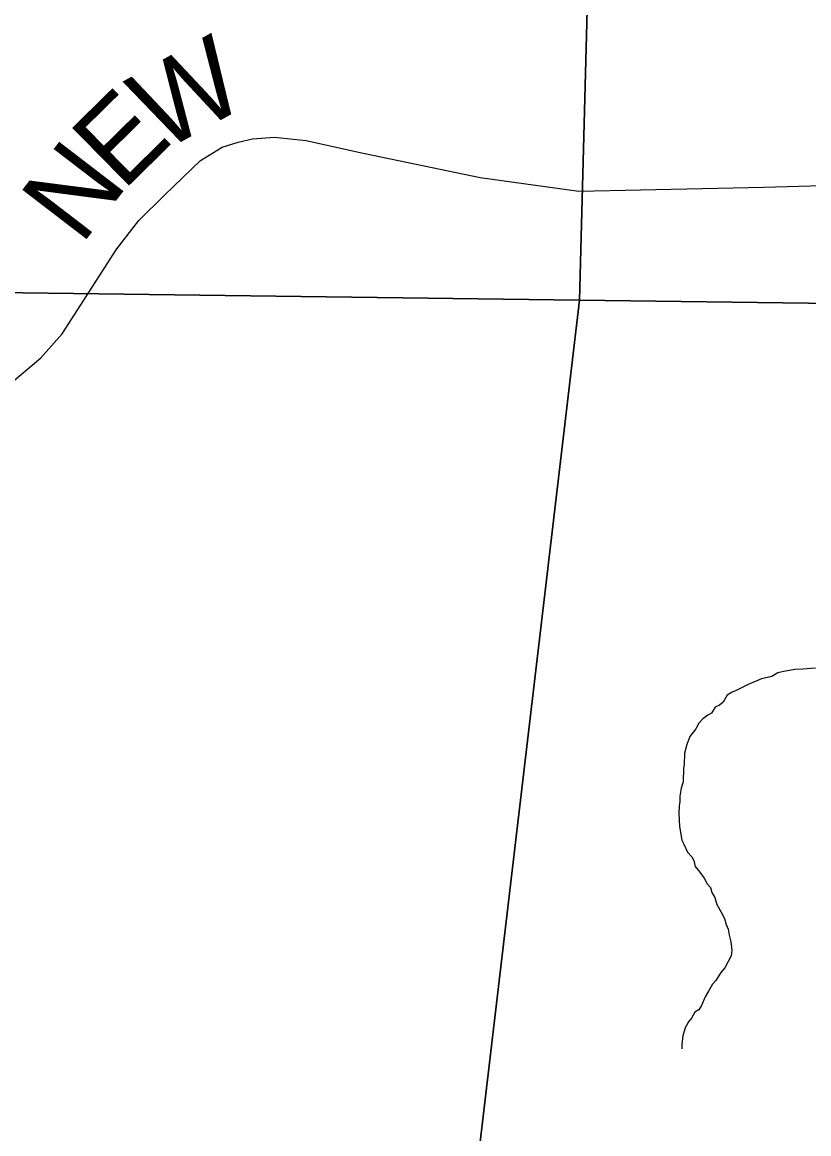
# Model space of a CAD drawing. Extents: x 0 to 34, y -2.3 to 22.
# Drawn here: x 3.123 to 3.675, y 15.821 to 16.601 of the extents above; entities that cross this region are included whole.
import ezdxf

# ---------------------------------------------------------------- set-up
doc = ezdxf.new("R2010")
doc.units = 0
for name, color, linetype in [('GM_X_County_Road', 7, 'Continuous'), ('GM_X_County_Road_Text', 7, 'Continuous'), ('GM_X_Minor_River', 7, 'Continuous'), ('GM_X_Section', 7, 'Continuous')]:
    doc.layers.add(name, color=color, linetype=linetype)

msp = doc.modelspace()

# ---------------------------------------------------------------- linework, layer by layer
at = {"layer": 'GM_X_County_Road'}
for p, q in [((3.26354, 16.51301), (3.27486, 16.51647)), ((3.27486, 16.51647), (3.28493, 16.51883)), ((3.28493, 16.51883), (3.30019, 16.51993)), ((3.30019, 16.51993), (3.32253, 16.51757)), ((3.32253, 16.51757), (3.35918, 16.50955)), ((3.24828, 16.50357), (3.26354, 16.51301)), ((3.35918, 16.50955), (3.44448, 16.49179)), ((3.22338, 16.47954), (3.24828, 16.50357)), ((3.64337, 16.48492), (3.8905, 16.49216)), ((3.44448, 16.49179), (3.51374, 16.48219)), ((3.51374, 16.48219), (3.64337, 16.48492)), ((3.20502, 16.46157), (3.22338, 16.47954)), ((3.18961, 16.44172), (3.20502, 16.46157)), ((3.15141, 16.38197), (3.18961, 16.44172)), ((3.13643, 16.36514), (3.15141, 16.38197)), ((3.07524, 16.3137), (3.13643, 16.36514))]:
    msp.add_line(p, q, dxfattribs=at)
at = {"layer": 'GM_X_Minor_River'}
for p, q in [((3.64894, 16.14178), (3.64167, 16.1401)), ((3.65319, 16.14432), (3.64894, 16.14178)), ((3.65625, 16.14499), (3.65319, 16.14432)), ((3.66504, 16.14662), (3.65625, 16.14499)), ((3.67075, 16.14683), (3.66504, 16.14662)), ((3.67952, 16.14771), (3.67075, 16.14683)), ((3.63243, 16.1362), (3.62394, 16.13189)), ((3.64167, 16.1401), (3.63243, 16.1362)), ((3.61777, 16.12866), (3.61496, 16.12381)), ((3.62125, 16.13083), (3.61777, 16.12866)), ((3.62394, 16.13189), (3.62125, 16.13083)), ((3.60916, 16.12018), (3.60676, 16.11607)), ((3.61224, 16.12161), (3.60916, 16.12018)), ((3.61496, 16.12381), (3.61224, 16.12161)), ((3.60056, 16.11208), (3.59781, 16.10912)), ((3.60405, 16.11463), (3.60056, 16.11208)), ((3.60676, 16.11607), (3.60405, 16.11463)), ((3.59579, 16.105), (3.59146, 16.09981)), ((3.59781, 16.10912), (3.59579, 16.105)), ((3.59146, 16.09981), (3.5894, 16.09418)), ((3.5877, 16.08815), (3.58747, 16.08018)), ((3.5894, 16.09418), (3.5877, 16.08815)), ((3.58747, 16.08018), (3.58701, 16.07753)), ((3.58701, 16.07753), (3.58674, 16.06804)), ((3.58546, 16.06352), (3.58454, 16.05785)), ((3.58674, 16.06804), (3.58546, 16.06352)), ((3.58454, 16.05785), (3.58443, 16.05406)), ((3.58396, 16.05103), (3.58381, 16.04572)), ((3.58443, 16.05406), (3.58396, 16.05103)), ((3.58381, 16.04572), (3.5843, 16.03659)), ((3.5843, 16.03659), (3.58593, 16.02704)), ((3.58593, 16.02704), (3.58737, 16.02434)), ((3.58737, 16.02434), (3.58986, 16.01857)), ((3.58986, 16.01857), (3.59281, 16.01544)), ((3.59281, 16.01544), (3.59426, 16.01274)), ((3.59426, 16.01274), (3.59528, 16.00853)), ((3.59528, 16.00853), (3.59858, 16.00463)), ((3.59858, 16.00463), (3.6015, 16.00036)), ((3.6015, 16.00036), (3.60367, 15.9965)), ((3.60367, 15.9965), (3.60587, 15.99378)), ((3.60587, 15.99378), (3.60691, 15.99033)), ((3.60691, 15.99033), (3.60909, 15.98684)), ((3.60909, 15.98684), (3.61047, 15.98186)), ((3.61047, 15.98186), (3.61335, 15.97646)), ((3.61335, 15.97646), (3.61589, 15.9722)), ((3.61589, 15.9722), (3.61691, 15.96799)), ((3.61691, 15.96799), (3.61833, 15.96453)), ((3.61833, 15.96453), (3.61896, 15.96033)), ((3.61896, 15.96033), (3.62035, 15.95574)), ((3.62035, 15.95574), (3.62094, 15.94964)), ((3.62094, 15.94964), (3.62045, 15.94585)), ((3.62045, 15.94585), (3.61603, 15.93763)), ((3.61327, 15.93429), (3.60969, 15.9287)), ((3.61603, 15.93763), (3.61327, 15.93429)), ((3.60733, 15.92611), (3.60453, 15.92126)), ((3.60969, 15.9287), (3.60733, 15.92611)), ((3.60213, 15.91715), (3.59967, 15.91114)), ((3.60453, 15.92126), (3.60213, 15.91715)), ((3.59769, 15.90817), (3.59497, 15.90635)), ((3.59967, 15.91114), (3.59769, 15.90817)), ((3.5906, 15.89964), (3.5882, 15.89553)), ((3.59257, 15.90224), (3.5906, 15.89964)), ((3.59497, 15.90635), (3.59257, 15.90224)), ((3.5882, 15.89553), (3.58652, 15.88989)), ((3.58652, 15.88989), (3.58596, 15.88382)), ((3.58596, 15.88382), (3.58587, 15.88078))]:
    msp.add_line(p, q, dxfattribs=at)
at = {"layer": 'GM_X_Section'}
for p, q in [((3.54075, 17.39533), (3.51408, 16.40568)), ((3.51408, 16.40568), (3.54075, 17.39533)), ((3.51408, 16.40568), (2.50896, 16.41908)), ((2.50896, 16.41908), (3.51408, 16.40568)), ((3.51408, 16.40568), (3.3991, 15.42954)), ((3.3991, 15.42954), (3.51408, 16.40568)), ((4.31696, 16.39529), (3.51408, 16.40568)), ((3.51408, 16.40568), (4.31696, 16.39529))]:
    msp.add_line(p, q, dxfattribs=at)

# ---------------------------------------------------------------- texts
at = {"layer": 'GM_X_County_Road_Text'}
for s, rotation, p in [('W', 28.80234, (3.22079, 16.50895)), ('E', 44.51968, (3.19379, 16.48161)), ('N', 52.50026, (3.16473, 16.44351))]:
    msp.add_text(s, height=0.05682, rotation=rotation, dxfattribs=at).set_placement(p)

doc.saveas('drawing.dxf')
